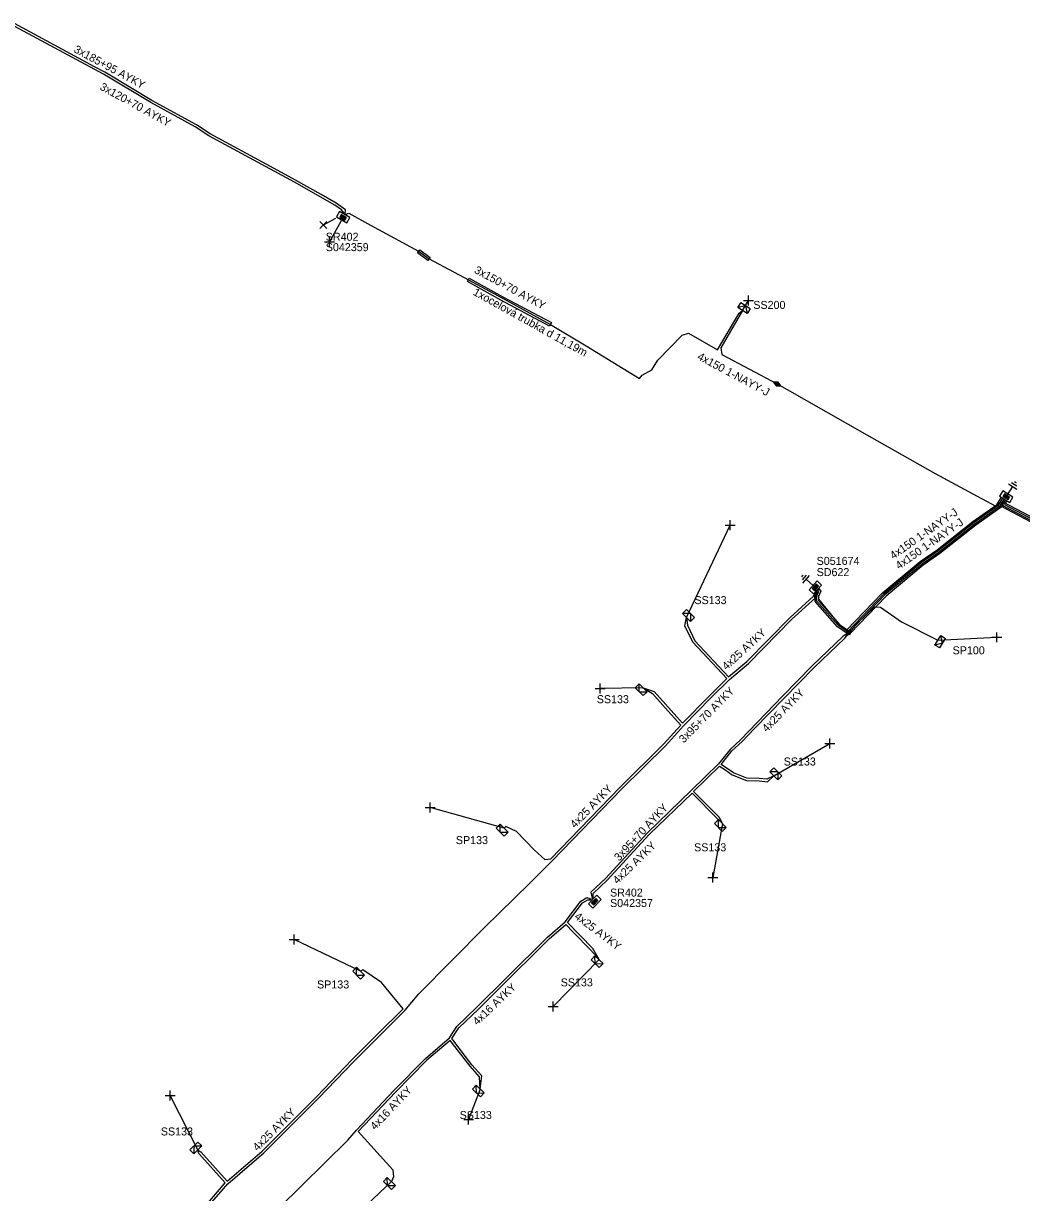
# Model space of a CAD drawing. Extents: x -737417 to -734469, y -1145580 to -1142703.
# Drawn here: x -736577.5 to -736452.8, y -1144288.6 to -1144142.5 of the extents above; entities that cross this region are included whole.
import ezdxf

# ---------------------------------------------------------------- set-up
doc = ezdxf.new("R2010")
doc.units = 0
for name, color, linetype in [('Vrstva 1', 7, 'Continuous'), ('Vrstva 14', 7, 'Continuous'), ('Vrstva 15', 7, 'Continuous'), ('Vrstva 19', 7, 'Continuous'), ('Vrstva 20', 7, 'Continuous'), ('Vrstva 21', 7, 'Continuous'), ('Vrstva 28', 7, 'Continuous'), ('Vrstva 29', 7, 'Continuous'), ('Vrstva 30', 7, 'Continuous'), ('Vrstva 31', 7, 'Continuous'), ('Vrstva 33', 7, 'Continuous'), ('Vrstva 34', 7, 'Continuous'), ('Vrstva 4', 7, 'Continuous'), ('Vrstva 5', 7, 'Continuous'), ('Vrstva 52', 7, 'Continuous'), ('Vrstva 54', 7, 'Continuous'), ('Vrstva 59', 7, 'Continuous'), ('Vrstva 6', 7, 'Continuous'), ('Vrstva 8', 7, 'Continuous'), ('Vrstva 9', 7, 'Continuous')]:
    doc.layers.add(name, color=color, linetype=linetype)

# ---------------------------------------------------------------- blocks, each defined once
blk = doc.blocks.new('NN870')
at = {"layer": 'Vrstva 4'}
for points in [[(0, -0.25), (0.5, 0), (0, 0.25), (-0.5, 0), (0, -0.25)], [(0.37, 0), (0, 0.19), (-0.36, 0), (0, -0.19), (0.37, 0)], [(0.24, 0), (0, 0.12), (-0.25, 0), (0, -0.12), (0.24, 0)], [(0.12, 0), (0, 0.06), (-0.13, 0), (0, -0.06), (0.12, 0)]]:
    blk.add_lwpolyline(points, dxfattribs=at)
blk = doc.blocks.new('NN800')
at = {"layer": 'Vrstva 1'}
for points in [[(-0.44, 0.44), (0.44, -0.44)], [(-0.44, -0.44), (0.44, 0.44)]]:
    blk.add_lwpolyline(points, dxfattribs=at)
blk = doc.blocks.new('NN620')
at = {"layer": 'Vrstva 8'}
for points in [[(0.75, 0), (-0.75, 0)], [(-0.75, 0), (-0.75, -0.75)], [(0.75, -0.75), (0.75, 0)], [(-0.75, -0.75), (0.75, -0.75)], [(0.37, -0.18), (-0.38, -0.18)], [(-0.38, -0.18), (-0.38, -0.56)], [(-0.38, -0.56), (0.37, -0.56)], [(0.32, -0.23), (-0.33, -0.23)], [(-0.33, -0.23), (-0.33, -0.51)], [(-0.33, -0.51), (0.32, -0.51)], [(0.27, -0.27), (-0.28, -0.27)], [(-0.28, -0.27), (-0.28, -0.46)], [(-0.28, -0.46), (0.27, -0.46)], [(0.23, -0.32), (-0.23, -0.32)], [(-0.23, -0.32), (-0.23, -0.42)], [(-0.23, -0.42), (0.23, -0.42)], [(-0.19, -0.37), (0.19, -0.37)], [(0.23, -0.42), (0.23, -0.32)], [(0.27, -0.46), (0.27, -0.27)], [(0.32, -0.51), (0.32, -0.23)], [(0.37, -0.56), (0.37, -0.18)]]:
    blk.add_lwpolyline(points, dxfattribs=at)
blk = doc.blocks.new('NN630')
at = {"layer": 'Vrstva 9'}
for points in [[(0, -0.7), (-0.7, 0)], [(-0.7, -0.7), (-0.7, 0), (0.7, 0), (0.7, -0.7)], [(-0.7, -0.7), (0.7, -0.7)], [(0, -0.7), (0.7, 0)]]:
    blk.add_lwpolyline(points, dxfattribs=at)
blk = doc.blocks.new('NN810')
at = {"layer": 'Vrstva 14'}
for points in [[(0, -0.64), (0, -1.89)], [(0.63, -1.89), (-0.62, -1.89)], [(0.39, -2.2), (-0.4, -2.2)], [(0, -2.52), (-0.12, -2.52)], [(0.14, -2.52), (0, -2.52)]]:
    blk.add_lwpolyline(points, dxfattribs=at)

msp = doc.modelspace()

# ---------------------------------------------------------------- linework, layer by layer
at = {"layer": 'Vrstva 20'}
for points in [[(-736528.28, -1144171.21), (-736527.98, -1144170.81), (-736526.68, -1144171.77), (-736526.98, -1144172.17)], [(-736522.04, -1144174.79), (-736521.8, -1144174.35), (-736517.61, -1144176.68), (-736511.52, -1144179.92), (-736511.76, -1144180.36), (-736517.85, -1144177.12)], [(-736474.7, -1144218.4), (-736470.15, -1144213.67), (-736465.45, -1144209.77), (-736463.36, -1144208.31), (-736458.87, -1144204.77), (-736455.43, -1144202.34), (-736455.09, -1144202.83), (-736458.51, -1144205.25), (-736463, -1144208.79), (-736465.09, -1144210.25), (-736469.73, -1144214.11), (-736474.26, -1144218.82)], [(-736438.71, -1144211.02), (-736429.92, -1144215.47), (-736424.15, -1144218.48), (-736413.18, -1144224.99), (-736413.48, -1144225.51), (-736424.45, -1144219), (-736430.2, -1144216.01), (-736438.99, -1144211.56), (-736446.3, -1144207.66), (-736455.4, -1144202.85), (-736455.12, -1144202.32), (-736446.02, -1144207.12)], [(-736478.2, -1144214.6), (-736475.54, -1144217.64), (-736474.37, -1144218.45), (-736474.59, -1144218.78), (-736475.8, -1144217.94), (-736478.6, -1144214.76), (-736478.62, -1144214.14), (-736478.35, -1144213.53), (-736478.45, -1144213.39), (-736478.13, -1144213.15), (-736477.89, -1144213.47), (-736478.22, -1144214.22)]]:
    msp.add_lwpolyline(points, close=True, dxfattribs=at)
at = {"layer": 'Vrstva 5'}
for points in [[(-736537.31, -1144166.32), (-736537.25, -1144165.82), (-736538.43, -1144164.99), (-736540.32, -1144163.93), (-736543.52, -1144162.11), (-736546.64, -1144160.43), (-736554.19, -1144156.33), (-736555.9, -1144155.19), (-736561.45, -1144152.15), (-736563.9, -1144150.7), (-736567.35, -1144148.62), (-736568.62, -1144147.94), (-736570.62, -1144146.88), (-736578.62, -1144142.53)], [(-736537.44, -1144166.23), (-736537.75, -1144165.81), (-736538.59, -1144165.25), (-736543.66, -1144162.37), (-736554.35, -1144156.59), (-736556.06, -1144155.45), (-736561.59, -1144152.41), (-736567.49, -1144148.88), (-736578.58, -1144142.91)], [(-736537.2, -1144166.38), (-736536.86, -1144166.23), (-736534.13, -1144167.73), (-736528.13, -1144171.01), (-736526.83, -1144171.97), (-736521.92, -1144174.57), (-736517.2, -1144177.12), (-736511.64, -1144180.14), (-736507.21, -1144182.84), (-736500.55, -1144186.89), (-736500.18, -1144186.49), (-736498.99, -1144185.82), (-736498.23, -1144184.62), (-736495.22, -1144181.49), (-736494.43, -1144181.26), (-736490.77, -1144183.34), (-736488.09, -1144178.75), (-736487.66, -1144178.4)], [(-736487.66, -1144178.4), (-736490.38, -1144183.07), (-736490.26, -1144183.89), (-736483.33, -1144187.59)], [(-736483.33, -1144187.59), (-736482.09, -1144188.29), (-736472.11, -1144193.94), (-736468.66, -1144195.91), (-736463.61, -1144198.78), (-736459.42, -1144201.03), (-736456.1, -1144202.82), (-736455.89, -1144202.68), (-736455.32, -1144201.73)], [(-736455.15, -1144201.83), (-736455.74, -1144202.8), (-736458.75, -1144204.93), (-736463.24, -1144208.47), (-736465.33, -1144209.93), (-736470.01, -1144213.82), (-736474.56, -1144218.55), (-736475.67, -1144217.79), (-736478.4, -1144214.68), (-736478.42, -1144214.18), (-736478.12, -1144213.5), (-736478.29, -1144213.27)], [(-736454.98, -1144201.94), (-736455.59, -1144202.95), (-736458.63, -1144205.09), (-736463.12, -1144208.63), (-736465.21, -1144210.09), (-736469.87, -1144213.96), (-736474.41, -1144218.68)], [(-736454.82, -1144202.04), (-736455.22, -1144202.72), (-736446.21, -1144207.48), (-736438.9, -1144211.38), (-736430.11, -1144215.83), (-736424.35, -1144218.83), (-736413.38, -1144225.34), (-736409.88, -1144227.2), (-736400.54, -1144231.77), (-736395.35, -1144234.41), (-736391.14, -1144236.6), (-736389.09, -1144237.99), (-736383.01, -1144240.58), (-736381.4, -1144240.53), (-736374.43, -1144243.3), (-736362.76, -1144248.02)], [(-736454.65, -1144202.15), (-736454.94, -1144202.65), (-736446.11, -1144207.3), (-736438.8, -1144211.2)], [(-736554.26, -1144290.18), (-736551.97, -1144287.53), (-736547.49, -1144283.69), (-736540.63, -1144276.83), (-736536.27, -1144272.28), (-736529.86, -1144265.88), (-736528.1, -1144263.8), (-736519.85, -1144255.47), (-736514.26, -1144250.03), (-736511.43, -1144247.18), (-736502.74, -1144238.2), (-736497.3, -1144232.8), (-736495.05, -1144230.3), (-736491.6, -1144226.83), (-736489.29, -1144224.54), (-736486.92, -1144222.5), (-736481.5, -1144216.99), (-736478.56, -1144214.3), (-736478.23, -1144213.25), (-736478.25, -1144213.23)], [(-736500.08, -1144225.55), (-736498.72, -1144226.04), (-736495.16, -1144229.97), (-736491.82, -1144226.61), (-736489.62, -1144224.39), (-736493.88, -1144219.85), (-736494.85, -1144217.81), (-736494.65, -1144216.78), (-736494.55, -1144217.75), (-736493.62, -1144219.67), (-736489.4, -1144224.2), (-736487.12, -1144222.28), (-736481.7, -1144216.77), (-736478.78, -1144214.1), (-736478.32, -1144213.34), (-736478.34, -1144213.32)], [(-736474.41, -1144218.68), (-736475.08, -1144219.12), (-736478.94, -1144222.81), (-736482.63, -1144226.57), (-736487.9, -1144232.06), (-736489.22, -1144233.25), (-736490.66, -1144235.07), (-736494.08, -1144238.41), (-736499.53, -1144243.7), (-736504.8, -1144249.4), (-736506.6, -1144251.11), (-736506.43, -1144251.88)], [(-736506.34, -1144251.79), (-736506.32, -1144251.25), (-736504.58, -1144249.6), (-736499.31, -1144243.91), (-736493.97, -1144238.74), (-736490.8, -1144241.92), (-736490.18, -1144242.53), (-736490.57, -1144241.72), (-736493.78, -1144238.52), (-736490.53, -1144235.36), (-736489.86, -1144235.77), (-736488.94, -1144236.45), (-736487.17, -1144237.13), (-736485.6, -1144237.19), (-736484.55, -1144237.29), (-736483.75, -1144236.55)], [(-736545.55, -1144290.55), (-736542.71, -1144287.76), (-736536.96, -1144282.09), (-736535.89, -1144280.82), (-736531.22, -1144275.87), (-736527.29, -1144271.87), (-736524.27, -1144269.31), (-736523.36, -1144267.87), (-736520.84, -1144265.48), (-736517.18, -1144261.83), (-736512.03, -1144256.72), (-736509.83, -1144254.82), (-736507.86, -1144252.21), (-736507.12, -1144251.77), (-736506.52, -1144251.98)], [(-736505.59, -1144259.53), (-736506.36, -1144258.14), (-736509.52, -1144254.89), (-736507.66, -1144252.43), (-736507, -1144252.05), (-736506.61, -1144252.07)], [(-736520.43, -1144275.7), (-736520.23, -1144274.04), (-736521.48, -1144272.66), (-736523.98, -1144269.4), (-736523.12, -1144268.07), (-736520.64, -1144265.7), (-736518.19, -1144263.24), (-736511.83, -1144256.94), (-736509.75, -1144255.14), (-736508.81, -1144256.08), (-736506.6, -1144258.34), (-736505.59, -1144259.53)], [(-736575.73, -1144310.73), (-736575.15, -1144310.83), (-736566.94, -1144302.42), (-736563.76, -1144299.04), (-736564.88, -1144297.81), (-736567.5, -1144295.4), (-736568.38, -1144295.76), (-736569.74, -1144297.09), (-736570.38, -1144297.25), (-736569.92, -1144296.85), (-736568.54, -1144295.5), (-736567.44, -1144295.06), (-736564.66, -1144297.59), (-736563.53, -1144298.84), (-736559.61, -1144295.08), (-736554.48, -1144289.98), (-736552.32, -1144287.4), (-736555.59, -1144283.76), (-736555.73, -1144283.31)]]:
    msp.add_lwpolyline(points, dxfattribs=at)
at = {"layer": 'Vrstva 52'}
for points in [[(-736483.75, -1144236.55), (-736484.63, -1144236.99), (-736485.58, -1144236.89), (-736487.11, -1144236.83), (-736488.8, -1144236.19), (-736490.31, -1144235.13), (-736489, -1144233.45), (-736487.7, -1144232.28), (-736486.19, -1144230.7), (-736478.72, -1144223.03), (-736474.88, -1144219.34), (-736473.32, -1144217.54), (-736471.15, -1144215.44), (-736470.44, -1144215.5), (-736467.81, -1144217.33), (-736463.26, -1144219.62)], [(-736500.08, -1144225.55), (-736498.9, -1144226.28), (-736497.34, -1144228.08), (-736495.36, -1144230.23), (-736497.52, -1144232.6), (-736502.96, -1144237.99), (-736507.93, -1144243.13), (-736511.65, -1144246.98), (-736512.3, -1144247.04), (-736513.7, -1144245.81), (-736515.9, -1144243.52), (-736517.23, -1144242.89), (-736517.45, -1144243.11)], [(-736555.73, -1144283.31), (-736555.35, -1144283.56), (-736552.07, -1144287.22), (-736547.69, -1144283.47), (-736543.39, -1144279.19), (-736540.85, -1144276.62), (-736536.49, -1144272.06), (-736533.23, -1144268.79), (-736530.08, -1144265.66), (-736532.77, -1144262.37), (-736535.1, -1144260.82), (-736535.38, -1144260.96)], [(-736520.43, -1144275.7), (-736520.53, -1144274.16), (-736521.71, -1144272.86), (-736524.18, -1144269.65), (-736527.09, -1144272.09), (-736531, -1144276.07), (-736535.67, -1144281.02), (-736531.34, -1144285.81), (-736531.25, -1144286.67), (-736531.54, -1144287.25)]]:
    msp.add_lwpolyline(points, dxfattribs=at)
at = {"layer": 'Vrstva 59'}
for points in [[(-736538.5, -1144166.9), (-736540.05, -1144167.73)], [(-736537.82, -1144167.19), (-736539.25, -1144169.83)], [(-736487.66, -1144178.4), (-736486.92, -1144177.17)], [(-736494.65, -1144216.78), (-736489.19, -1144205.25)], [(-736463.26, -1144219.62), (-736455.88, -1144219.25)], [(-736500.08, -1144225.55), (-736505.44, -1144225.63)], [(-736483.75, -1144236.55), (-736476.75, -1144232.5)], [(-736517.45, -1144243.11), (-736526.69, -1144240.5)], [(-736490.18, -1144242.53), (-736491.38, -1144249.25)], [(-736535.38, -1144260.96), (-736543.69, -1144257)], [(-736505.59, -1144259.53), (-736511.31, -1144265.38)], [(-736555.73, -1144283.31), (-736559.19, -1144276.5)], [(-736520.43, -1144275.7), (-736521.88, -1144279.5)], [(-736531.54, -1144287.25), (-736538.38, -1144293.75)]]:
    msp.add_lwpolyline(points, dxfattribs=at)
at = {"layer": 'Vrstva 9'}
msp.add_lwpolyline([(-736478.15, -1144213.99), (-736478.16, -1144214.5), (-736476.71, -1144216.27), (-736475.44, -1144217.81)], dxfattribs=at)

# ---------------------------------------------------------------- block references
at = {"layer": 'Vrstva 15'}
for p, rotation in [((-736454.9, -1144201.99), 147.8975888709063), ((-736478.29, -1144213.27), -132.30094991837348)]:
    msp.add_blockref('NN810', p, dxfattribs=dict(at, rotation=rotation))
at = {"layer": 'Vrstva 19'}
for p, rotation in [((-736483.33, -1144187.59), -28.098227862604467), ((-736474.41, -1144218.68), 46.11456391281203)]:
    msp.add_blockref('NN870', p, dxfattribs=dict(at, rotation=rotation))
at = {"layer": 'Vrstva 28'}
for p, rotation in [((-736537.38, -1144166.43), -30.068583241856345), ((-736454.9, -1144201.99), 147.8975888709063), ((-736478.29, -1144213.27), -132.30094996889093), ((-736506.38, -1144252.02), 45.80693049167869)]:
    msp.add_blockref('NN620', p, dxfattribs=dict(at, rotation=rotation))
at = {"layer": 'Vrstva 31'}
for p, rotation in [((-736487.66, -1144178.4), 147.65704170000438), ((-736494.65, -1144216.78), 135.17775273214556), ((-736463.26, -1144219.62), 58.97934723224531), ((-736500.08, -1144225.55), -45.314325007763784), ((-736483.75, -1144236.55), 134.70516947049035), ((-736517.45, -1144243.11), -45.15117507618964), ((-736490.18, -1144242.53), -45.40443327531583), ((-736505.59, -1144259.53), -43.984797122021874), ((-736535.38, -1144260.96), -44.77136662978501), ((-736520.43, -1144275.7), -43.855855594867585), ((-736555.73, -1144283.31), -135.18246955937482), ((-736531.54, -1144287.25), -44.17507222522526)]:
    msp.add_blockref('NN630', p, dxfattribs=dict(at, rotation=rotation))
at = {"layer": 'Vrstva 34'}
msp.add_blockref('NN800', (-736540.05, -1144167.73), dxfattribs=at)
for p, rotation in [((-736539.25, -1144169.83), 45), ((-736486.92, -1144177.17), 45), ((-736489.19, -1144205.25), 44.99999995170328), ((-736455.88, -1144219.25), 45), ((-736505.44, -1144225.63), 44.99999995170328), ((-736476.75, -1144232.5), 45), ((-736526.69, -1144240.5), 44.99999995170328), ((-736491.38, -1144249.25), 45), ((-736543.69, -1144257), 44.99999995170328), ((-736511.31, -1144265.38), 45), ((-736559.19, -1144276.5), 44.99999995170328), ((-736521.88, -1144279.5), 45)]:
    msp.add_blockref('NN800', p, dxfattribs=dict(at, rotation=rotation))

# ---------------------------------------------------------------- texts
at = {"layer": 'Vrstva 21'}
msp.add_text('1xocelová trubka d 11,19m', height=1, rotation=330.916, dxfattribs=at).set_placement((-736521.42, -1144176.4))
at = {"layer": 'Vrstva 29'}
for s, p in [('S042359', (-736539.73, -1144170.99)), ('S051674', (-736478.4, -1144210.2)), ('S042357', (-736504.21, -1144252.95))]:
    msp.add_text(s, height=1, dxfattribs=at).set_placement(p)
at = {"layer": 'Vrstva 30'}
for s, p in [('SR402', (-736539.73, -1144169.69)), ('SD622', (-736478.4, -1144211.6)), ('SR402', (-736504.21, -1144251.65))]:
    msp.add_text(s, height=1, dxfattribs=at).set_placement(p)
at = {"layer": 'Vrstva 33'}
for s, p in [('SS200', (-736486.31, -1144178.21)), ('SS133', (-736493.67, -1144215.1)), ('SP100', (-736461.41, -1144221.37)), ('SS133', (-736505.87, -1144227.48)), ('SS133', (-736482.52, -1144235.27)), ('SP133', (-736523.48, -1144245.09)), ('SS133', (-736493.71, -1144245.99)), ('SS133', (-736510.38, -1144262.87)), ('SP133', (-736540.82, -1144263.13)), ('SS133', (-736523, -1144279.44)), ('SS133', (-736560.34, -1144281.5))]:
    msp.add_text(s, height=1, dxfattribs=at).set_placement(p)
at = {"layer": 'Vrstva 54'}
for s, rotation, p in [('4x25 AYKY', 45.787, (-736484.63, -1144231.17)), ('4x25 AYKY', 45.974, (-736508.6, -1144243.17)), ('4x16 AYKY', 46.668, (-736533.57, -1144280.89)), ('4x25 AYKY', 44.853, (-736548.27, -1144283.52))]:
    msp.add_text(s, height=1, rotation=rotation, dxfattribs=at).set_placement(p)
at = {"layer": 'Vrstva 6'}
for s, rotation, p in [('3x185+95 AYKY', 331.615, (-736571.31, -1144146.07)), ('3x120+70 AYKY', 331.248, (-736568.06, -1144150.75)), ('3x150+70 AYKY', 331.62, (-736521.27, -1144173.65)), ('4x150 1-NAYY-J', 331.902, (-736493.4, -1144184.46)), ('4x150 1-NAYY-J', 34.924, (-736468.82, -1144209.55)), ('4x150 1-NAYY-J', 34.95, (-736468.11, -1144210.81)), ('4x25 AYKY', 42.444, (-736489.67, -1144223.41)), ('3x95+70 AYKY', 45.256, (-736495.01, -1144232.53)), ('3x95+70 AYKY', 47.245, (-736503.08, -1144247.29)), ('4x25 AYKY', 44.03, (-736503.3, -1144250.15)), ('4x25 AYKY', 322.953, (-736508.75, -1144254.31)), ('4x16 AYKY', 43.584, (-736520.8, -1144267.8))]:
    msp.add_text(s, height=1, rotation=rotation, dxfattribs=at).set_placement(p)

doc.saveas('drawing.dxf')
